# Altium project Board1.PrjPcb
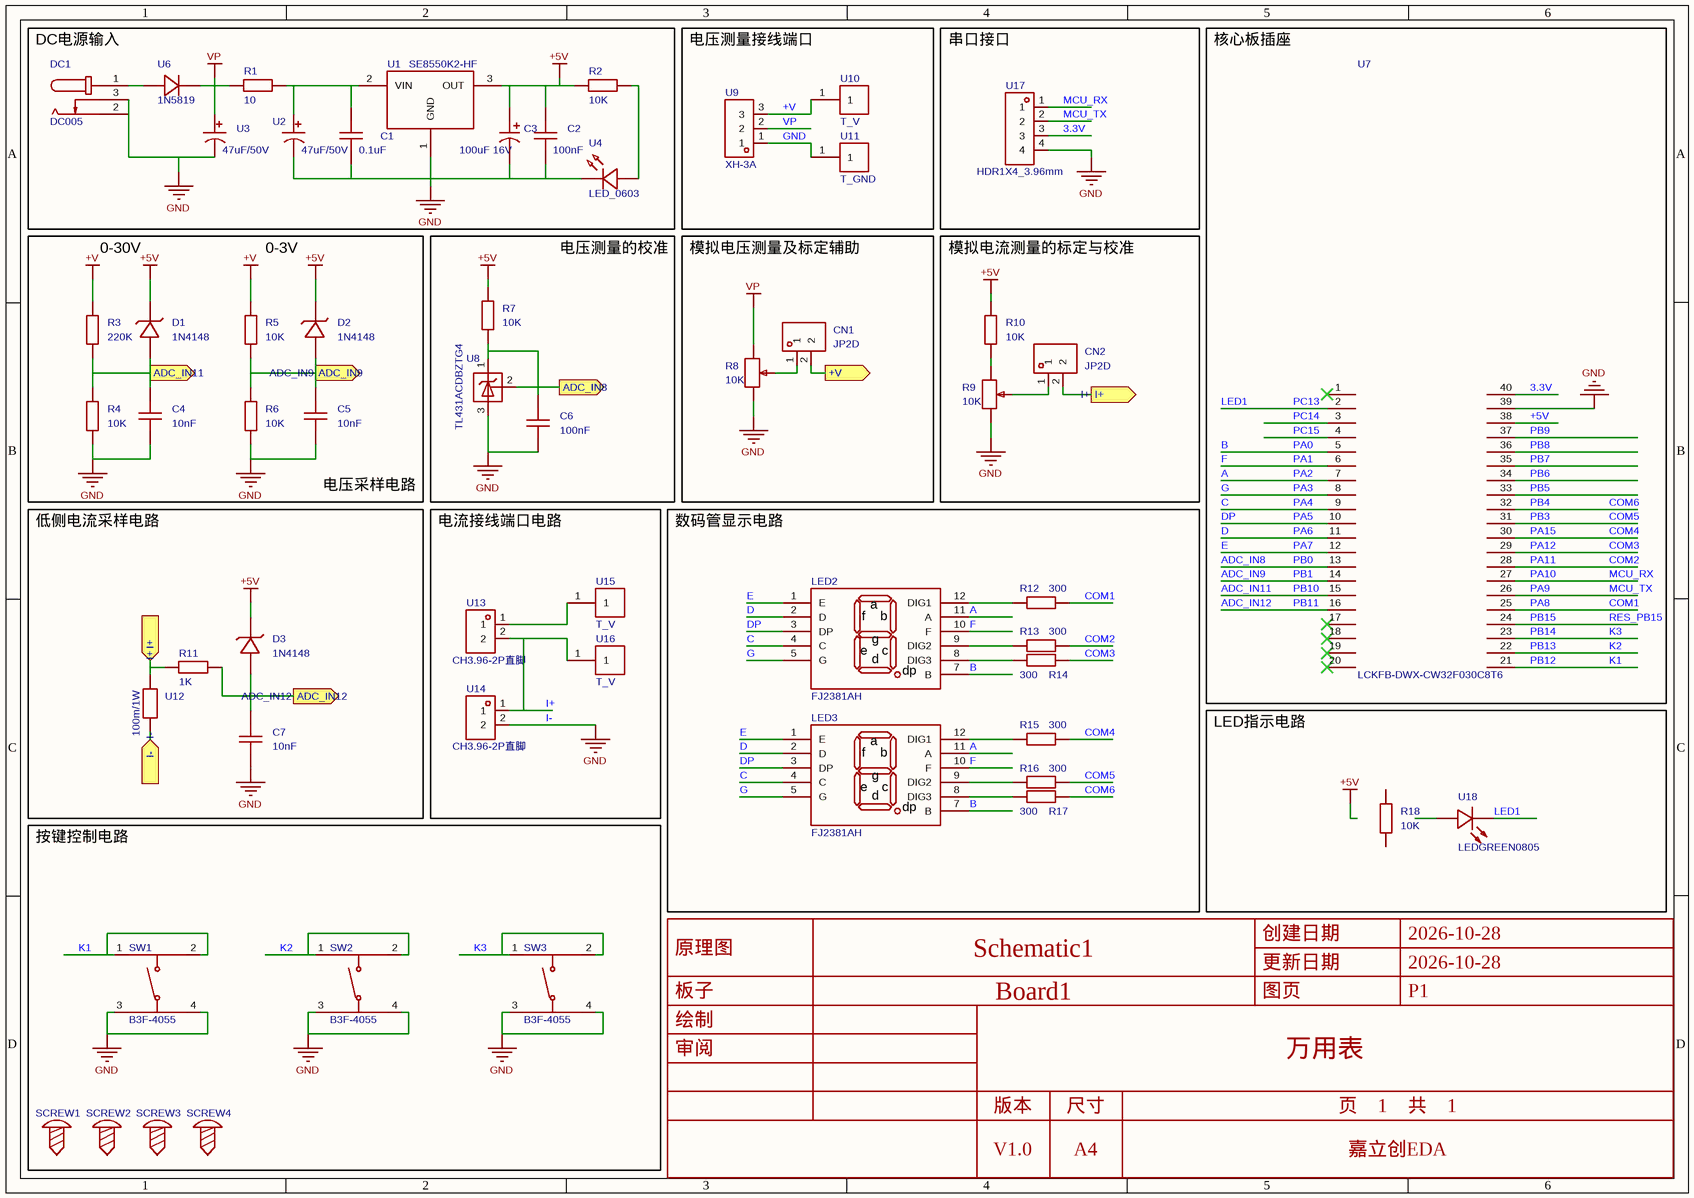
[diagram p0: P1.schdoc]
1 sheet, 57 parts. Net scope: flat (ports and power ports of the same name join across sheets).
Board file: PCB1.pcbdoc

## Sheet P1.schdoc
size 297 x 209 mm; Symbol: Drawing-Symbol_A4; Device: Drawing-Symbol_A4; Company: 嘉立创EDA; Version: V1.0; Page Size: A4; @Project Name: 万用表; @Update Date: 2026-10-28; @Create Date: 2026-10-28; @Board Name: Board1; @Page Name: P1; @Create Time: 20:47:09; @Page Count: 1; @Page No: 1; @Schematic Name: Schematic1; @Update Time: 20:47:09; @Assembly Variant: Basic; Border: 1; Title Block Position: 3; Size: A4; Width: 1170; Height: 825; Region Start: 1; X Region Count: 6; Y Region Count: 4; Blade Width: 10

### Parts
C1  0.1uF  [C0603]
C2  100nF  [C0603]
C3  100uF 16V  [CAP-SMD_L6.0-W3.2-FD]
C4  10nF  [C0603]
C5  10nF  [C0603]
C6  100nF  [C0603]
C7  10nF  [C0603]
CN1  JP2D  [CONN-TH_2P-P3.96-V]
CN2  JP2D  [CONN-TH_2P-P3.96-V]
D1  1N4148  [SOD-123_L2.7-W1.7-LS3.8-RD]
D2  1N4148  [SOD-123_L2.7-W1.7-LS3.8-RD]
D3  1N4148  [SOD-123_L2.7-W1.7-LS3.8-RD]
DC1  DC005  [DC-IN-TH_DC005]
LED2  FJ2381AH  [LED-SEG-TH_FJ2381AH]
LED3  FJ2381AH  [LED-SEG-TH_FJ2381AH]
R1  10  [R0603]
R2  10K  [R0603]
R3  220K  [R0603]
R4  10K  [R0603]
R5  10K  [R0603]
R6  10K  [R0603]
R7  10K  [R0603]
R8  10K  [RES-ADJ-TH_3296W]
R9  10K  [RES-ADJ-TH_3296W]
R10  10K  [R0603]
R11  1K  [R0603]
R12  300  [R0603]
R13  300  [R0603]
R14  300  [R0603]
R15  300  [R0603]
R16  300  [R0603]
R17  300  [R0603]
R18  10K  [R0603]
SCREW1  (no value)  [M2螺丝]
SCREW2  (no value)  [M2螺丝]
SCREW3  (no value)  [M2螺丝]
SCREW4  (no value)  [M2螺丝]
SW1  B3F-4055  [SW-TH_4P-L12.0-W12.0-P5.00-LS12.5]
SW2  B3F-4055  [SW-TH_4P-L12.0-W12.0-P5.00-LS12.5]
SW3  B3F-4055  [SW-TH_4P-L12.0-W12.0-P5.00-LS12.5]
U1  SE8550K2-HF  [SOT-89-3_L4.5-W2.5-P1.50-LS4.2-BR]
U2  47uF/50V  [CAP-TH_BD8.0-P3.50-D0.6-FD-2]
U3  47uF/50V  [CAP-TH_BD8.0-P3.50-D0.6-FD-2]
U4  LED_0603  [LED0603-RD_RED]
U6  1N5819  [SMA_L4.3-W2.6-LS5.1-RD]
U7  LCKFB-DWX-CW32F030C8T6  [DIP-40_L53.34-W15.24-P2.54-LS15.24]
U8  TL431ACDBZTG4  [SOT-23-3_L3.0-W1.7-P0.95-LS2.9-BR]
U9  XH-3A  [CONN-TH_3P-P2.50_C9900023074]
U10  T_V  [TH-1_C9900016725]
U11  T_GND  [TH-1_C9900016725]
U12  100m/1W  [R1206]
U13  CH3.96-2P直脚  [CONN-TH_CH3.96-2P]
U14  CH3.96-2P直脚  [CONN-TH_CH3.96-2P]
U15  T_V  [TH-1_C9900016725]
U16  T_V  [TH-1_C9900016725]
U17  HDR1X4_3.96mm  [CONN-TH_4P-P3.96_FWF39601-S04S22W1B]
U18  LEDGREEN0805  [LED0805-R-RD_GREEN]

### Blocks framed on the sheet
DC电源输入: C1-C3 DC1 R1 R2 U1-U4 U6
电压测量接线端口: U9-U11
串口接口: U17
核心板插座: U7
电压测量的校准: C6 R7 U8
模拟电压测量及标定辅助: CN1 R8
模拟电流测量的标定与校准: CN2 R9 R10
电流接线端口电路: U13-U16
数码管显示电路: LED2 LED3 R12-R17
LED指示电路: R18 U18
按键控制电路: SCREW1-SCREW4 SW1-SW3

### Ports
+V (out), ADC_IN8 (out), ADC_IN9 (out), ADC_IN11 (out), ADC_IN12 (out), I+ (in), I+ (out), I- (in)

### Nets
+5V: C2.2 C3.1 D1.1(K) D2.1(K) D3.1(K) R2.1 R7.2 R10.2 U1.3(OUT) U7.38
+V: R3.2 R5.2 U9.3 U10.1
GND: C1.1 C2.1 C3.2 C4.1 C5.1 C6.1 C7.1 DC1.2 DC1.3 R4.1 R6.1 R8.1 R9.1 SW1.3 SW1.4 SW2.3 SW2.4 SW3.3 SW3.4 U1.1(GND) U2.2 U3.2 U4.1(K) U7.39 U8.3(A) U9.1 U11.1 U12.2 U14.2 U17.4 ; port I-  [also labelled I-]
VP: R1.1 R8.3 U3.1 U6.1(K) U9.2
3.3V: U7.40 U17.3
A: LED2.11(A) LED3.11(A) U7.7  [also labelled PA2]
ADC_IN8: U7.13  [also labelled PB0]
ADC_IN9: C5.2 D2.2(A) R5.1 R6.2 U7.14 ; port ADC_IN9  [also labelled PB1]
ADC_IN11: U7.15  [also labelled PB10]
ADC_IN12: C7.2 D3.2(A) R11.1 U7.16 ; port ADC_IN12  [also labelled PB11]
B: LED2.7(B) LED3.7(B) U7.5  [also labelled PA0]
C: LED2.4(C) LED3.4(C) U7.9  [also labelled PA4]
COM1: R12.1 U7.25  [also labelled PA8]
COM2: R13.1 U7.28  [also labelled PA11]
COM3: R14.1 U7.29  [also labelled PA12]
COM4: R15.1 U7.30  [also labelled PA15]
COM5: R16.1 U7.31  [also labelled PB3]
COM6: R17.1 U7.32  [also labelled PB4]
D: LED2.2(D) LED3.2(D) U7.11  [also labelled PA6]
DP: LED2.3(DP) LED3.3(DP) U7.10  [also labelled PA5]
E: LED2.1(E) LED3.1(E) U7.12  [also labelled PA7]
F: LED2.10(F) LED3.10(F) U7.6  [also labelled PA1]
G: LED2.5(G) LED3.5(G) U7.8  [also labelled PA3]
I+: CN2.2 R11.2 U12.1 U13.2 U14.1 U16.1 ; port I+
K1: SW1.1 SW1.2 U7.21  [also labelled PB12]
K2: SW2.1 SW2.2 U7.22  [also labelled PB13]
K3: SW3.1 SW3.2 U7.23  [also labelled PB14]
LED1: U7.2 U18.2(K)  [also labelled PC13]
MCU_RX: U7.27 U17.1  [also labelled PA10]
MCU_TX: U7.26 U17.2  [also labelled PA9]
PB5: U7.33
PB6: U7.34
PB7: U7.35
PB8: U7.36
PB9: U7.37
PB15: U7.24  [also labelled RES_PB15]
PC14: U7.3
PC15: U7.4
NetC1_2: C1.2 R1.2 U1.2(VIN) U2.1
NetC4_2: C4.2 D1.2(A) R3.1 R4.2 ; port ADC_IN11
NetC6_2: C6.2 R7.1 U8.1(K) U8.2(R) ; port ADC_IN8
NetCN1_1: CN1.1 R8.2
NetCN1_2: CN1.2 ; port +V
NetCN2_1: CN2.1 R9.2
NetDC1_1: DC1.1 U6.2(A)
NetLED2_8: LED2.8(DIG3) R14.2
NetLED2_9: LED2.9(DIG2) R13.2
NetLED2_12: LED2.12(DIG1) R12.2
NetLED3_8: LED3.8(DIG3) R17.2
NetLED3_9: LED3.9(DIG2) R16.2
NetLED3_12: LED3.12(DIG1) R15.2
NetR2_2: R2.2 U4.2(A)
NetR9_3: R9.3 R10.1
NetU13_1: U13.1 U15.1

Not connected (* = marked no-connect by the designer): R18 1 2; SCREW1 1; SCREW2 1; SCREW3 1; SCREW4 1; U7 1(0)* 17(0)* 18(0)* 19(0)* 20(0)*; U18 1(A)

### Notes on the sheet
- 0-30V
- 0-3V
- (near C5) 电压采样电路
- 低侧电流采样电路

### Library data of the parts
C1 C2 = CAP_0603: Symbol: Capacitance; ConvertToPcb: yes; ModelId: ac125912035d415993ca9572d50418b10819f05c4eef4c71ace90d822a990e87; ModelName: C0603_L1.6-W0.8-H0.8; ModelTransform: 62.992,31.496,0,0,0,0,0,0,0
C3 = 100uF 16V: AddInBom: yes; ModelId: f3109eabdf8740af9f36b97adf252a880819f05c4eef4c71ace90d822a990e87; ModelName: CAP-SMD_L6.0-W3.2-RD; ModelTransform: 237.7948,125.984,0,0,0,0,0,0,0
C4-C7 = CAP_0603: Symbol: Capacitance; 3D Model: ac125912035d415993ca9572d50418b10819f05c4eef4c71ace90d822a990e87; 3D Model Transform: 62.992,31.496,0,0,0,0,0,0,0; ConvertToPcb: yes; ModelName: C0603_L1.6-W0.8-H0.8
CN1 CN2 = JP2D: AddInBom: yes; ModelId: 2eb2d044c10a453aa78fdaaf8421e3e00819f05c4eef4c71ace90d822a990e87; ModelTransform: 311.8104,334.645,0,0,0,0,0,-23.622,-149.606
D1-D3 = 1N4148: Symbol: 1N4148_C9900009645; AddInBom: yes; ModelId: b455d3bf1dad47d3a75f9a76b08071c60819f05c4eef4c71ace90d822a990e87; ModelTransform: 145.669,64.961,0,0,0,0,0,0,0
DC1 = DC005: 连接器类型:DC电源插座;安装方式:弯插;触点内径:2mm;触点外径:6.3mm;额定电流:500mA;额定电压:12V;工作温度:-30℃~+70℃;; Manufacturer: SHOU HAN(首韩); Symbol: DC005_C431533; AddInBom: yes; ModelId: f168fe383f964e0ea2af0127ff6ac7b40819f05c4eef4c71ace90d822a990e87; ModelTransform: 366.141,553.149,0,270,0,0,-141.734,88.583,-149.606; Connector Type: DC电源插座; Inside Contact Diameter: 2mm; Outside Contact Diameter: 6.3mm; Current Rating: 500mA; Voltage Rating (Max): 12V; Body Height: 10.9mm
LED2 LED3 = FJ2381AH: 数码管位数:3位;字符尺寸(英寸):0.28;LED极性:共阴;发光颜色:红色;耗散功率(Pd):-;; Manufacturer: 志浩; AddInBom: yes; ModelId: b22df6d78d6c4251bddd51b739e5becf0819f05c4eef4c71ace90d822a990e87; ModelName: LED-SEG-TH_11P-L22.5-W10.0-H6.1-P2.54-S7.62; ModelTransform: 885.825,393.7,0,0,0,0,0,0,-137.795; Number of Characters: 3位; Digit/Alpha Size(inch): 0.28; Display Type: 7段; LED Polarity: 共阴; Illumination Color: 红色
R1 R2 = Res_0603: Symbol: 电阻; ConvertToPcb: yes; ModelId: fc143cca1e79419f9cd78b61e9279f080819f05c4eef4c71ace90d822a990e87; ModelTransform: 31.8897,63.7794,0,90,0,0,0,0,0
R3-R7 R10-R18 = Res_0603: Symbol: 电阻; 3D Model: fc143cca1e79419f9cd78b61e9279f080819f05c4eef4c71ace90d822a990e87; 3D Model Transform: 31.8897,63.7794,0,90,0,0,0,0,0; ConvertToPcb: yes
R8 R9 = 精密电位器 3296W/50欧姆: 阻值:-;功率:-;; Symbol: Precision potentiometer 3296W/50ohm; AddInBom: yes; ModelId: 3664f7b541aa4725a8b6d3b7a961f0780819f05c4eef4c71ace90d822a990e87; ModelTransform: 374.015,188.976,0,90,0,0,2.362,0.005,-137.795
SCREW1-SCREW4 = M2螺丝: Symbol: 螺丝孔; ConvertToPcb: yes
SW1-SW3 = B3F-4055: Symbol: B3F-4055_C9900023790; AddInBom: yes; ModelId: 7313330cfbcf439981db3a700e07703f0819f05c4eef4c71ace90d822a990e87; ModelTransform: 542.968,472.47937,0,0,0,0,0,0.005,-137.795
U1 = SE8550K2-HF: 输出极性:正极;工作电压:35V;输出电压:5V;输出电流:200mA;电源纹波抑制比(PSRR):80dB;输出类型:固定;; Manufacturer: SEAWARD(思旺); Symbol: SE8550-HF; AddInBom: yes; ModelId: 6db690b7897d4d18a30d90c1b89525ee0819f05c4eef4c71ace90d822a990e87; ModelName: SOT-89-3_L4.3-W2.5-H1.6-LS4.1-P1.50; ModelTransform: 161.417,169.291,0,180,0,0,-18.661,0,0; Output Configuration: 正极; Voltage - Supply: 35V; Output Voltage: 5V; Output Current: 200mA; Power Supply Rejection Ratio (PSRR): 80dB; Voltage Dropout: 300mV@(100mA); standby current: 2.5uA; Output Type: 固定
U2 U3 = 电解电容100uF/50V: AddInBom: yes; ModelId: fd7be3432f664311809e69e3b3557c130819f05c4eef4c71ace90d822a990e87; ModelTransform: 314.96,315.3537,0,90,0,0,0,0,-196.85
U4 = LED_0603: AddInBom: yes; ModelId: 74041d3a270d435c8600a9ab9b7641c00819f05c4eef4c71ace90d822a990e87; ModelTransform: 63.7794,31.496,0,0,0,0,0,-0.002,0
U6 = 1N5819: Symbol: 1N5819_C9900008009; AddInBom: yes; ModelId: 1d20a911e9694ba6aaf6e9207164e4da0819f05c4eef4c71ace90d822a990e87; ModelTransform: 196.4563,102.362,0,0,0,0,0.001,-0.001,0
U7 = LCKFB-DWX-CW32F030C8T6: 搭载Cortex-M0+内核,程序存储容量64KB,RAM总容量8KB,最高64MHz主频,提供高效的计算能力和稳定的运行环境。; Manufacturer: 立创开发板; AddInBom: yes; ModelId: 65c6a085ee334f57b7e20e20cdb6a0820819f05c4eef4c71ace90d822a990e87; ModelTransform: 2114.856,898.9982,0,90,0,0,0,-7.874,-236.22
U8 = TL431ACDBZTG4: 输出类型:可调;输入电压:-;输出电流:100mA;精度:±1%;; Manufacturer: TI(德州仪器); AddInBom: yes; ModelId: 89cb27a44ab2466697082bb9fd73a7d00819f05c4eef4c71ace90d822a990e87; ModelName: SOT-23-3L_L2.9-W1.6-H1.1-LS2.8-P0.95; ModelTransform: 114.173,110.236,0,90,0,0,0,0,0; Output Type: 可调; Output Current: 100mA; Tolerance: ±1%; Reference Type: 并联
U9 = XH-3A_C9900023074: AddInBom: yes; ModelId: f64135b5aae74472b0d9f88aaedb98e80819f05c4eef4c71ace90d822a990e87; ModelTransform: 394.094,224.409,0,0,0,0,0,18.661,-118.11
U10 U11 U15 U16 = NEW_FOOTPRINT: AddInBom: yes; ModelId: de06a563d2fa4cfb9506e2ac83ef3f720819f05c4eef4c71ace90d822a990e87; ModelTransform: 216.35,236.22004,0,0,0,0,0,-33.465,-98.425
U12 = ARG06BTC2151: AddInBom: yes; ModelId: 89a1f13db2384da588040e0b3c55bf660819f05c4eef4c71ace90d822a990e87; ModelName: R1206_L3.2-W1.6-H0.6; ModelTransform: 125.984,62.992,0,0,0,0,0,0,0
U13 U14 = CH3.96-2P直脚: AddInBom: yes; ModelId: df1c1c596aa749818eee4fbdc34283bf0819f05c4eef4c71ace90d822a990e87; ModelTransform: 314.96,437.401,0,0,0,0,0,0,-137.795
U17 = HDR1X4_3.96mm: AddInBom: yes; ModelId: d1971f11994642cab35ac1c5dad2b2580819f05c4eef4c71ace90d822a990e87; ModelTransform: 623.6208,325.1962,0,0,0,0,-0.001,-26.378,-137.795
U18 = LEDGREEN0805: AddInBom: yes; ModelId: 8baff3af93dc43f9ae0855f3d9d6093c0819f05c4eef4c71ace90d822a990e87; ModelTransform: 78.74,49.209,0,0,0,0,0,0,0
